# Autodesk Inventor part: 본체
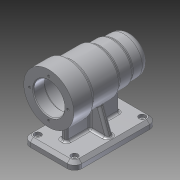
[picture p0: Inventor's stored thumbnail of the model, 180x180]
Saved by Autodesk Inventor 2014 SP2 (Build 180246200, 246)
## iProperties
Created: 2016-06
Part Number: 본체
Material: 알루미늄 6061
Document SubType Name: Modeling
Designer: 달님반
Density: 2.71 g/cm^3
Appearance: 알루미늄 - 평지
Author: 달님반
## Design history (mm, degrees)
sketch "스케치1"
  geometry: L1 (0, 0)-(112, 0); L2 (0, 0)-(0, 25); L3 (0, 25)-(25, 25); L4 (25, 25)-(25, 27); L5 (25, 27)-(45, 27); L6 (45, 27)-(45, 30); L7 (45, 30)-(84, 30); L8 (84, 30)-(84, 34); L9 (84, 34)-(112, 34); L10 (112, 34)-(112, 0); 1 further point
  constraints: 20 end point, 4 parallel, 3 vertical, 2 perpendicular, 1 coincident, 1 horizontal
  dimensions: "d0" = 112 distance between parallel lines of L10 L2; "d1" = 84 distance between parallel lines of L2 L8; "d2" = 45 distance between parallel lines of L2 L6; "d3" = 25 distance between parallel lines of L2 L4; "d4" = 68 diameter of L9 L1; "d5" = 60 diameter of L7 L1; "d6" = 54 diameter of L5 L1; "d7" = 50 diameter of L3 L1
revolve "회전1" sketch "스케치1" stored, may be unused: angle "d8" = 90 deg
sketch "스케치2"
  geometry: L1 (0, 0)-(112, 0); L2 (112, -34)-(112, 34) reference; L3 (6, 0)-(6, 10.5); L4 (6, 10.5)-(9, 10.5); L5 (9, 10.5)-(9, 16); L6 (9, 16)-(13, 16); L7 (13, 16)-(13, 17.5); L8 (13, 17.5)-(31, 17.5); L9 (31, 17.5)-(31, 21); L10 (31, 21)-(43, 21); L11 (43, 21)-(43, 24); L12 (43, 24)-(97, 24); L13 (97, 24)-(97, 21); L14 (97, 21)-(112, 21); L15 (112, 21)-(112, 0); 1 further point
  constraints: 28 end point, 7 parallel, 2 collinear, 2 horizontal, 2 point on line, 2 vertical, 1 coincident, 1 midpoint, 1 perpendicular
  dimensions: "d9" = 42 diameter of L14 L1; "d10" = 48 diameter of L12 L1; "d11" = 42 diameter of L10 L1; "d12" = 35 diameter of L8 L1; "d13" = 32 diameter of L6 L1; "d14" = 21 diameter of L4 L1; "d15" = 3 distance of L3.end L4.end; "d16" = 15 distance of L13.end L14.end; "d17" = 54 distance of L11.end L12.end; "d18" = 12 distance of L9.end L10.end; "d19" = 18 distance of L7.end L8.end; "d20" = 4 distance of L5.end L6.end
revolve "회전2" sketch "스케치2" stored, may be unused: angle "d21" = 90 deg
node "작업 평면1"
sketch "스케치3"
  geometry: L1 (-25, 0)-(25, 0); L2 (35, 10)-(35, 102); L3 (25, 112)-(-25, 112); L4 (-35, 102)-(-35, 10); L5 (34, 112)-(-34, 112) reference; A1 r 10 centre (-25, 10) between (-35, 10) and (-25, 0); A2 r 10 centre (25, 10) between (25, 0) and (35, 10); A3 r 10 centre (25, 102) between (35, 102) and (25, 112); A4 r 10 centre (-25, 102) between (-25, 112) and (-35, 102); 6 further points
  constraints: 8 end point, 8 point on circle, 8 tangent, 6 point on line, 4 centre point, 3 equal radius, 2 midpoint, 2 parallel, 1 coincident, 1 collinear, 1 horizontal, 1 perpendicular
  dimensions: "d23" = 112 distance of point (-35, 112) point (-35, 0); "d24" = 70 distance of point (-35, 0) point (35, 0); "d25" = 10 radius of A1
extrude "돌출1" join sketch "스케치3" distance "d26" = 10; taper "d27" = 0 deg
node "작업 평면2"
sketch "스케치4"
  geometry: L1 (25, -60)-(-25, -60) reference; L2 (35, -60)-(25, -60) reference; L3 (-25, -60)-(-35, -60) reference; L4 (0, 0)-(0, -60); L5 (35, -70)-(35, -60) reference; L6 (15.509, -25.68)-(28, -60); L7 (-15.509, -25.68)-(-28, -60); L8 (-28, -60)-(28, -60); A1 r 30 centre (0, 0) between (15.509, -25.68) and (-15.509, -25.68) reference; A2 r 30 centre (0, 0) between (-15.509, -25.68) and (15.509, -25.68); 1 further point
  constraints: 8 end point, 4 point on circle, 2 point on line, 1 centre point, 1 collinear, 1 concentric, 1 midpoint, 1 other
  dimensions: "d31" = 7 distance from line of L6.end L5; "d32" = 110 deg angle of L2 L6
extrude "돌출2" join sketch "스케치4" stored distance "d33" = 8; taper "d34" = 0 deg
sketch "스케치5"
  geometry: L1 (0, -25)-(0, 25) reference; L2 (0, 25)-(25, 25) reference; L3 (25, 25)-(25, 27) reference; L4 (25, 27)-(45, 27) reference; L5 (45, 27)-(45, 30) reference; L6 (45, 30)-(84, 30) reference; L7 (84, 30)-(84, 34) reference; L8 (84, 34)-(112, 34) reference; L9 (112, 34)-(112, 21) reference; L10 (112, 21)-(97, 21) reference; L11 (97, 21)-(97, 24) reference; L12 (97, 24)-(43, 24) reference; L13 (43, 24)-(43, 21) reference; L14 (43, 21)-(31, 21) reference; L15 (31, 21)-(31, 17.5) reference; L16 (31, 17.5)-(13, 17.5) reference; L17 (13, 17.5)-(13, 16) reference; L18 (13, 16)-(9, 16) reference; L19 (9, 16)-(9, 10.5) reference; L20 (9, 10.5)-(6, 10.5) reference; L21 (6, 10.5)-(6, -10.5) reference; L22 (6, -10.5)-(9, -10.5) reference; L23 (9, -10.5)-(9, -16) reference; L24 (9, -16)-(13, -16) reference; L25 (13, -16)-(13, -17.5) reference; L26 (13, -17.5)-(31, -17.5) reference; L27 (31, -17.5)-(31, -21) reference; L28 (31, -21)-(43, -21) reference; L29 (43, -21)-(43, -24) reference; L30 (43, -24)-(97, -24) reference; L31 (97, -24)-(97, -21) reference; L32 (97, -21)-(112, -21) reference; L33 (112, -21)-(112, -34) reference; L34 (112, -34)-(84, -34) reference; L35 (84, -34)-(84, -30) reference; L36 (84, -30)-(60, -30) reference; L37 (60, -30)-(60, -60) reference; L38 (60, -60)-(112, -60) reference; L39 (112, -60)-(112, -70) reference; L40 (112, -70)-(0, -70) reference; L41 (0, -70)-(0, -60) reference; L42 (0, -60)-(52, -60) reference; L43 (52, -60)-(52, -30) reference; L44 (52, -30)-(45, -30) reference; L45 (45, -30)-(45, -27) reference; L46 (45, -27)-(25, -27) reference; L47 (25, -27)-(25, -25) reference; L48 (25, -25)-(0, -25) reference; L49 (92, -34)-(92, -60); L50 (20, -25)-(20, -60); 1 further point
  constraints: 4 end point, 4 point on line, 1 perpendicular
  dimensions: "d37" = 90 deg angle of L38 L49; "d39" = 20 distance from line of L39 L49.end; "d40" = 20 distance between parallel lines of L50 L41
  node "절단 모서리 투영1"
feature "리브1" dims "d41" = 1, "d42" = 8, "d43" = 0, "d44" = 0, "d45" = 1, "d46" = 1
feature "리브2" dims "d47" = 1, "d48" = 8, "d49" = 0, "d50" = 0, "d51" = 1, "d52" = 1
sketch "스케치6"
  geometry: C1 r 21 at (0, 0) reference; C2 r 34 at (0, 0) reference; A1 r 26 centre (0, 0) between (0, 26) and (-26, 0); 2 further points
  constraints: 4 point on circle, 2 horizontal alignment, 2 vertical alignment, 1 centre point, 1 coincident
  dimensions: "d53" = 52 diameter of A1
hole "구멍1" sketch "스케치6" at (0, 26), (-26, 0), (0, -26), (26, 0) diameter "d54" = 3.242; stored, may be unused: countersink angle "d58" = 90 deg, drill point angle "d60" = 118 deg; dims "d55" = 8, "d56" = 4, "d57" = 2, "d59" = 11
sketch "스케치7"
  geometry: A1 r 10 centre (25, 10) between (25, 0) and (35, 10) reference; A2 r 10 centre (25, 102) between (35, 102) and (25, 112) reference; A3 r 10 centre (-25, 102) between (-25, 112) and (-35, 102) reference; A4 r 10 centre (-25, 10) between (-35, 10) and (-25, 0) reference; 1 further point
hole "구멍2" sketch "스케치7" at (-25, 102), (25, 102), (-25, 10), (25, 10) diameter "d61" = 5; stored, may be unused: countersink angle "d65" = 90 deg, drill point angle "d67" = 118 deg; dims "d62" = 8, "d63" = 9, "d64" = 4, "d66" = 11
chamfer "모따기1" distance "d68" = 4; stored, may be unused: second distance "d69" = 2, angle "d70" = 45 deg
chamfer "모따기2" distance "d71" = 1; stored, may be unused: second distance "d72" = 2, angle "d73" = 45 deg
fillet "모깎기1" dims "d74" = 10
fillet "모깎기2" dims "d75" = 3
fillet "모깎기3" dims "d76" = 3
fillet "모깎기4" dims "d77" = 3
fillet "모깎기5" dims "d78" = 0.3
node "작업 평면3"
sketch "스케치8"
  geometry: L1 (10, -70)-(102, -70) reference; L2 (112, -34)-(112, 34) reference; 2 further points
  constraints: 1 other
  dimensions: "d80" = 70 distance from line of L1 point (64, 0); "d81" = 48 distance from line of L2 point (64, 0)
feature "엠보싱1" sketch "스케치8" dims "d9" = 42, "d10" = 48, "d11" = 42, "d12" = 35, "d13" = 32, "d14" = 21, "d15" = 3, "d16" = 15, "d17" = 54, "d18" = 12, "d19" = 18, "d20" = 4, "d82" = 0.5, "d83" = 0
node "솔리드1"
other parameters: "d28" = 56, "d79" = 49.5
